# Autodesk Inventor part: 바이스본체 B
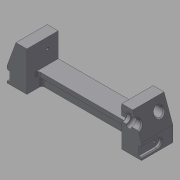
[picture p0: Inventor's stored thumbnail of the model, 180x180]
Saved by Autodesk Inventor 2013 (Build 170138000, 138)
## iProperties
Created: 2017-04
Part Number: 바이스본체 B
Material: 일반
Document SubType Name: Modeling
Designer: mduedu
Density: 1 g/cm^3
Author: mduedu
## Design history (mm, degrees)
sketch "스케치1"
  geometry: L1 (-75, 0)-(75, 0); L2 (-75, 0)-(-75, 17); L3 (-53, 17)-(53, 17); L4 (75, 17)-(75, 0); L5 (-75, 17)-(-65.173, 44); L6 (-65.173, 44)-(-53, 44); L7 (-53, 44)-(-53, 17); L8 (0, 0)-(0, 17); L9 (75, 17)-(65.173, 44); L10 (65.173, 44)-(53, 44); L11 (53, 44)-(53, 17); 1 further point
  constraints: 22 end point, 4 perpendicular, 2 horizontal alignment, 2 midpoint, 2 symmetric about line, 1 coincident, 1 collinear, 1 horizontal, 1 vertical
  dimensions: "d0" = 150 distance of L1.start L1.end; "d1" = 17 distance of L1.start L2.end; "d2" = 27 distance of L3.start L6.end; "d3" = 22 distance of L3.start L2.end; "d4" = 70 deg angle of L3 L5; "d54" = 20 deg angle of L9 L4
extrude "돌출1" new body sketch "스케치1" stored distance "d5" = 70; taper "d6" = 0 deg
sketch "스케치2"
  geometry: L1 (0, 70)-(106, 70) reference; L2 (106, 70)-(106, 0) reference; L3 (106, 0)-(0, 0) reference; L4 (0, 47)-(106, 47); L5 (106, 47)-(106, 23); L6 (106, 23)-(0, 23); L7 (0, 23)-(0, 47); L8 (0, 70)-(0, 0) reference; 2 further points
  constraints: 8 end point, 2 parallel, 2 point on line, 1 horizontal, 1 horizontal alignment, 1 midpoint, 1 perpendicular
  dimensions: "d7" = 24 distance between parallel lines of L6 L4
extrude "돌출2" cut sketch "스케치2" stored distance "d9" = 70; taper "d10" = 0 deg
sketch "스케치3"
  geometry: L1 (22, -23)-(128, -23) reference; L2 (128, -47)-(22, -47) reference; L3 (22, -18)-(128, -18); L4 (128, -52)-(22, -52); L5 (22, -18)-(22, -52); L6 (128, -18)-(128, -52); 1 further point
  constraints: 8 end point, 3 parallel, 2 point on line, 1 perpendicular
  dimensions: "d11" = 5 distance between parallel lines of L3 L1; "d12" = 5 distance between parallel lines of L4 L2
extrude "돌출3" cut sketch "스케치3" distance "d13" = 12; taper "d14" = 0 deg
fillet "모깎기1" dims "d15" = 3, "d16" = 3
sketch "스케치4"
  geometry: L1 (103, 23)-(3, 23) reference; L2 (0, 26)-(0, 0) reference; L3 (106, 0)-(0, 0) reference; L4 (106, 26)-(106, 0) reference; L5 (96, 0)-(90, 0); L6 (90, 0)-(90, 19.5); L7 (96, 19.5)-(96, 0); L8 (90, 19.5)-(96, 19.5); A1 r 3 centre (3, 26) between (0, 26) and (3, 23) reference; A2 r 3 centre (103, 26) between (103, 23) and (106, 26) reference; 1 further point
  constraints: 8 end point, 2 perpendicular, 1 horizontal, 1 parallel, 1 point on line
  dimensions: "d17" = 10 distance between parallel lines of L7 L4; "d18" = 6 distance between parallel lines of L7 L6; "d27" = 3.5 distance between parallel lines of L8 L1
extrude "돌출4" join sketch "스케치4" distance "d19" = 12; taper "d20" = 0 deg
chamfer "모따기1" distance "d21" = 3; stored, may be unused: second distance "d22" = 2, angle "d23" = 45 deg
chamfer "모따기2" distance "d24" = 3; stored, may be unused: second distance "d25" = 2, angle "d26" = 45 deg
sketch "스케치5"
  geometry: L1 (-15.5, 35.8)-(-15.5, -25.8) reference; L2 (19.5, 0)-(0, 0) reference; C1 r 6.5 at (9.5, 15); 1 further point
  constraints: 1 centre point
  dimensions: "d28" = 13 diameter of C1; "d30" = 15 distance from line of C1.centre L2; "d31" = 25 distance from line of C1.centre L1
extrude "돌출5" cut sketch "스케치5" stored distance "d32" = 12; taper "d33" = 0 deg
sketch "스케치6"
  geometry: C1 r 5 at (-10, 15); C2 r 5 at (-60, 15); A1 r 6.5 centre (-10, 15) between (-15.766, 12) and (-4.234, 12) reference; A2 r 6.5 centre (-60, 15) between (-65.766, 12) and (-54.234, 12) reference; 1 further point
  constraints: 2 centre point, 2 coincident
  dimensions: "d34" = 10 diameter of C1; "d35" = 10 diameter of C2 (= d34)
extrude "돌출6" cut sketch "스케치6" stored distance "d36" = 12; taper "d37" = 0 deg
chamfer "모따기3" distance "d38" = 1; stored, may be unused: second distance "d39" = 2, angle "d40" = 45 deg
chamfer "모따기4" distance "d41" = 1; stored, may be unused: second distance "d42" = 2, angle "d43" = 45 deg
sketch "스케치7"
  geometry: L1 (-35, 35.8)-(-35, -25.8) reference; L2 (-70, 0)-(0, 0) reference; C1 r 5 at (-35, 15); 1 further point
  constraints: 1 centre point, 1 point on line
  dimensions: "d44" = 10 diameter of C1; "d45" = 15 distance from line of C1.centre L2
extrude "돌출7" cut sketch "스케치7" stored distance "d46" = 12; taper "d47" = 0 deg
chamfer "모따기5" distance "d48" = 1; stored, may be unused: second distance "d49" = 2, angle "d50" = 45 deg
node "작업축1"
sketch "스케치8"
  geometry: L1 (-105, 32)-(105, 32) reference; L2 (58, 32)-(64, 32); L3 (64, 32)-(64, 40); L4 (64, 40)-(58, 40); L5 (58, 40)-(58, 32); L6 (53, 38)-(53, 26) reference; 1 further point
  constraints: 8 end point, 2 parallel, 1 horizontal, 1 perpendicular, 1 point on line
  dimensions: "d51" = 5 distance from line of L6 L2.start; "d52" = 6 distance of L3.end L4.end; "d53" = 16 diameter of L4 L1
revolve "회전1" sketch "스케치8" stored, may be unused: angle "d55" = 90 deg
fillet "모깎기2"
chamfer "모따기6" distance "d56" = 1; stored, may be unused: second distance "d57" = 2, angle "d58" = 45 deg
sketch "스케치9"
  geometry: L1 (17.5, 3)-(52.5, 3); L2 (52.5, 13)-(17.5, 13); L3 (70, 0)-(0, 0) reference; L4 (17.5, 8)-(52.5, 8); A1 r 5 centre (17.5, 8) between (17.5, 13) and (17.5, 3); A2 r 5 centre (52.5, 8) between (52.5, 3) and (52.5, 13); 3 further points
  constraints: 6 end point, 4 point on circle, 3 tangent, 2 centre point, 2 midpoint, 2 parallel, 1 horizontal, 1 vertical alignment
  dimensions: "d59" = 35 distance of L4.start L4.end; "d61" = 5 radius of A2; "d62" = 8 distance between parallel lines of L3 L4
extrude "돌출8" cut sketch "스케치9" distance "d63" = 3; taper "d64" = 0 deg
chamfer "모따기7" distance "d65" = 1; stored, may be unused: second distance "d66" = 2, angle "d67" = 45 deg
chamfer "모따기8" distance "d68" = 1; stored, may be unused: second distance "d69" = 2, angle "d70" = 45 deg
feature "분할1"
sketch "스케치10"
  geometry: A1 r 5 centre (0, 0) between (0, 5) and (0, -5) reference; 1 further point
  constraints: 1 coincident
hole "구멍1" sketch "스케치10" at (0, 0) diameter "d71" = 2.459; stored, may be unused: countersink angle "d75" = 90 deg, drill point angle "d77" = 120 deg; dims "d72" = 4.5, "d73" = 4, "d74" = 2, "d76" = 6
sketch "스케치11"
  geometry: L1 (0, 0)-(0, 27) reference; L2 (0, 27)-(-35, 27) reference; 2 further points
  dimensions: "d78" = 12 distance from line of point (-12, 15.5) L1; "d79" = 11.5 distance from line of point (-12, 15.5) L2
hole "구멍2" sketch "스케치11" at (-12, 15.5) diameter "d80" = 3.242; stored, may be unused: countersink angle "d84" = 90 deg, drill point angle "d86" = 120 deg; dims "d81" = 6, "d82" = 4, "d83" = 2, "d85" = 8
node "솔리드1"
mirror "대칭1"
mirror "대칭2"
mirror "대칭3"
mirror "대칭4"
node "투영된 루프1"
